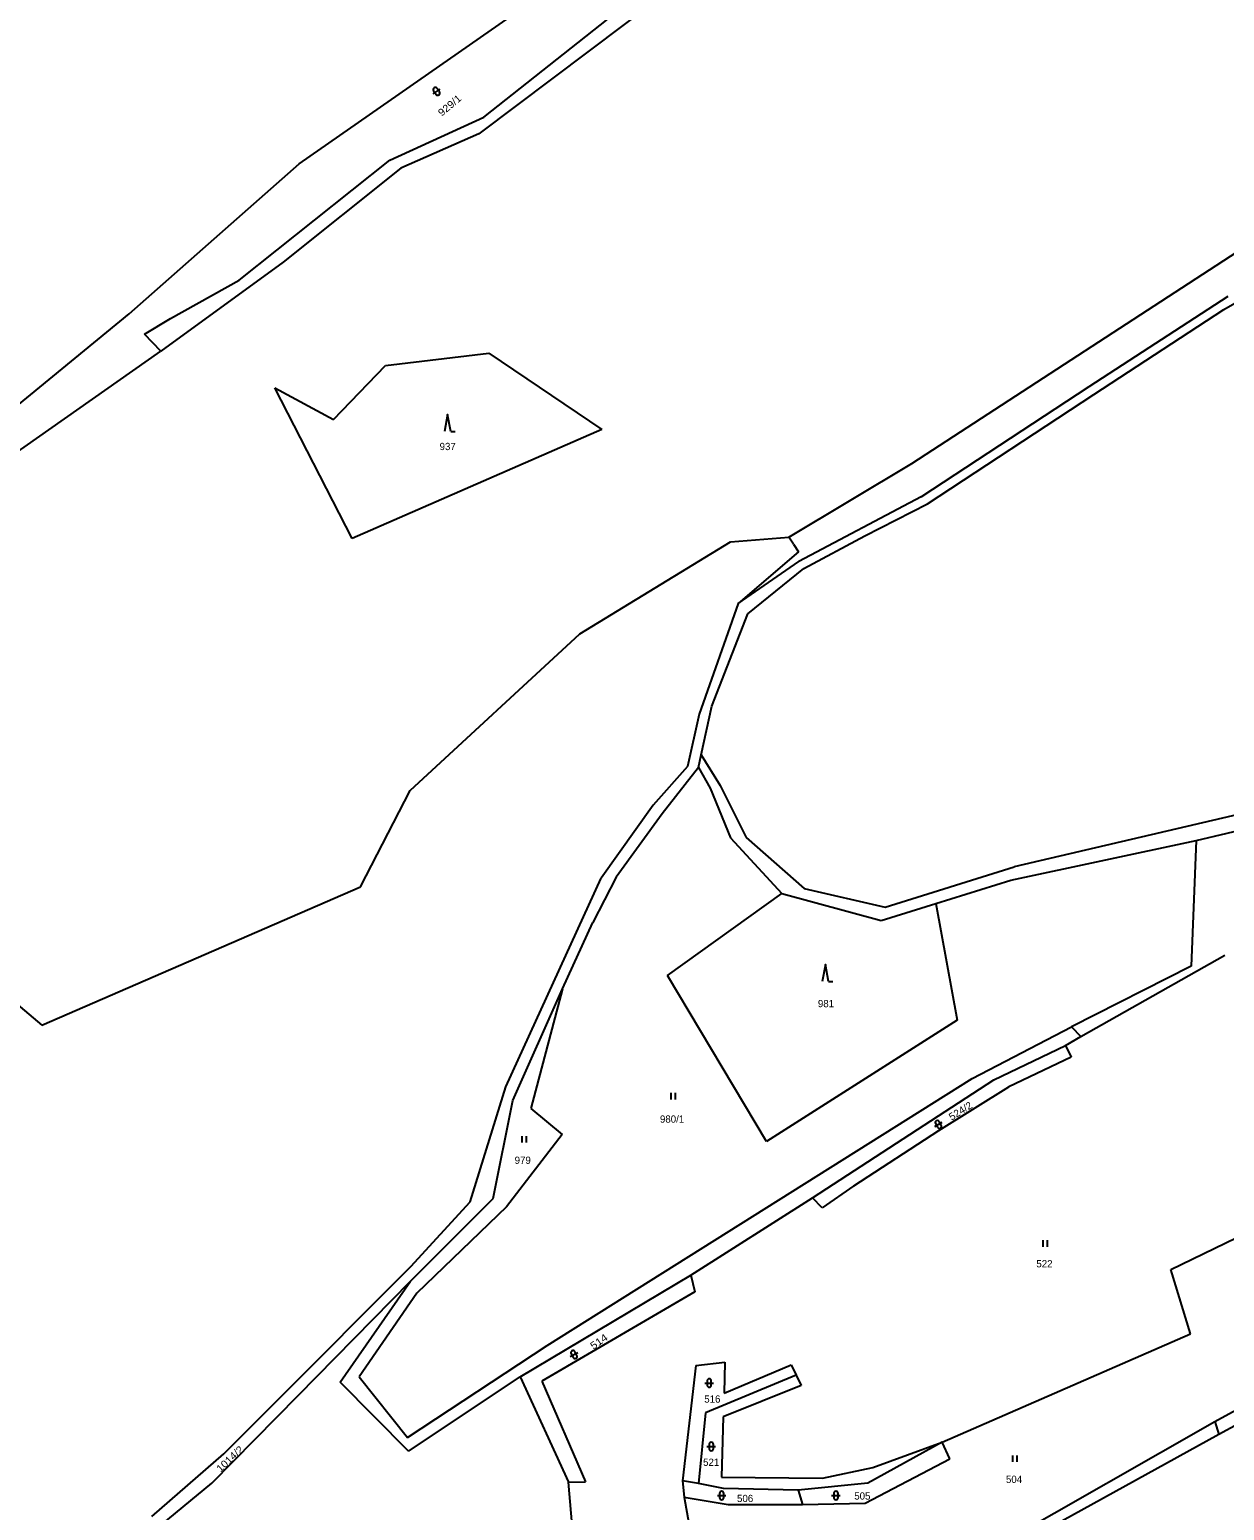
# Model space of a CAD drawing. Extents: x -744132 to -742433, y -984679 to -982287.
# Drawn here: x -743720.7 to -743440.4, y -983707.4 to -983360 of the extents above; entities that cross this region are included whole.
import ezdxf

# ---------------------------------------------------------------- set-up
doc = ezdxf.new("R2010")
doc.units = 0
doc.header["$LTSCALE"] = 0.68
doc.layers.add('1', color=7, linetype='Continuous', lineweight=25)
doc.layers.add('3', color=7, linetype='Continuous', lineweight=25)
doc.layers.add('2', color=7, linetype='Continuous')

msp = doc.modelspace()

# ---------------------------------------------------------------- linework, layer by layer
at = {"layer": '1'}
for p, q in [((-743614.1, -983380.55), (-743560.21, -983337.88)), ((-743563.34, -983345.36), (-743615.25, -983384.5)), ((-743657.43, -983391.5), (-743594.46, -983347.58)), ((-743636.13, -983390.66), (-743614.1, -983380.55)), ((-743615.25, -983384.5), (-743633.58, -983392.53)), ((-743697.32, -983426.73), (-743657.43, -983391.5)), ((-743671.51, -983418.82), (-743636.13, -983390.66)), ((-743513.68, -983461.85), (-743405.43, -983391.3)), ((-743633.58, -983392.53), (-743661.19, -983414.55)), ((-743440.48, -983425.67), (-743400.81, -983402.85)), ((-743661.19, -983414.55), (-743689.92, -983435.46)), ((-743687.58, -983427.84), (-743671.51, -983418.82)), ((-743472.08, -983443.75), (-743439.53, -983422.56)), ((-743471.02, -983445.6), (-743440.48, -983425.67)), ((-743723.53, -983448.22), (-743697.32, -983426.73)), ((-743693.75, -983431.44), (-743687.58, -983427.84)), ((-743689.92, -983435.46), (-743693.75, -983431.44)), ((-743729.35, -983463.19), (-743689.92, -983435.46)), ((-743637.19, -983438.85), (-743612.94, -983435.94)), ((-743612.94, -983435.94), (-743586.41, -983453.84)), ((-743649.36, -983451.49), (-743637.19, -983438.85)), ((-743663.12, -983444.04), (-743649.36, -983451.49)), ((-743645.01, -983479.43), (-743663.12, -983444.04)), ((-743511.48, -983469.61), (-743472.08, -983443.75)), ((-743510.03, -983471.31), (-743471.02, -983445.6)), ((-743586.41, -983453.84), (-743645.01, -983479.43)), ((-743542.57, -983479.1), (-743513.68, -983461.85)), ((-743511.48, -983469.61), (-743540.2, -983484.82)), ((-743524.75, -983478.76), (-743510.03, -983471.31)), ((-743591.6, -983501.75), (-743556.27, -983480.21)), ((-743556.27, -983480.21), (-743542.57, -983479.1)), ((-743541.49, -983480.77), (-743542.57, -983479.1)), ((-743541.49, -983480.77), (-743540.27, -983482.58)), ((-743539.01, -983486.42), (-743524.75, -983478.76)), ((-743540.27, -983482.58), (-743554.45, -983494.7)), ((-743554.45, -983494.7), (-743540.2, -983484.82)), ((-743552.2, -983497.05), (-743539.01, -983486.42)), ((-743554.45, -983494.7), (-743563.6, -983520.61)), ((-743560.64, -983518.75), (-743552.2, -983497.05)), ((-743631.38, -983538.54), (-743591.6, -983501.75)), ((-743563.12, -983530.19), (-743560.64, -983518.75)), ((-743563.6, -983520.61), (-743566.33, -983532.9)), ((-743563.76, -983533.13), (-743563.12, -983530.19)), ((-743563.12, -983530.19), (-743558.67, -983537.33)), ((-743566.33, -983532.9), (-743574.36, -983541.99)), ((-743563.76, -983533.13), (-743572.31, -983544.01)), ((-743563.76, -983533.13), (-743561.01, -983537.99)), ((-743558.67, -983537.33), (-743552.59, -983549.58)), ((-743643.04, -983561.17), (-743631.38, -983538.54)), ((-743561.01, -983537.99), (-743556.24, -983549.65)), ((-743409.37, -983537.63), (-743489.7, -983556.43)), ((-743446.97, -983550.29), (-743405.77, -983540.41)), ((-743574.36, -983541.99), (-743586.57, -983559.09)), ((-743572.31, -983544.01), (-743583.1, -983558.89)), ((-743556.24, -983549.65), (-743544.2, -983562.66)), ((-743552.59, -983549.58), (-743538.97, -983561.54)), ((-743490.48, -983559.54), (-743446.97, -983550.29)), ((-743446.97, -983550.29), (-743448.16, -983579.71)), ((-743762.21, -983556.11), (-743717.8, -983593.58)), ((-743519.94, -983565.92), (-743489.7, -983556.43)), ((-743717.8, -983593.58), (-743643.04, -983561.17)), ((-743608.97, -983608.04), (-743586.57, -983559.09)), ((-743583.1, -983558.89), (-743588.55, -983569.5)), ((-743538.97, -983561.54), (-743519.94, -983565.92)), ((-743508.06, -983565.05), (-743490.48, -983559.54)), ((-743571, -983581.95), (-743544.2, -983562.66)), ((-743544.2, -983562.66), (-743520.91, -983569.03)), ((-743520.91, -983569.03), (-743508.06, -983565.05)), ((-743508.06, -983565.05), (-743503.04, -983592.39)), ((-743595.62, -983585.1), (-743588.55, -983569.5)), ((-743474.03, -983596.28), (-743440.28, -983577.14)), ((-743547.82, -983620.87), (-743571, -983581.95)), ((-743448.16, -983579.71), (-743476.24, -983593.96)), ((-743607.28, -983611.24), (-743595.62, -983585.1)), ((-743595.62, -983585.1), (-743603.12, -983613.14)), ((-743503.04, -983592.39), (-743547.82, -983620.87)), ((-743499.57, -983606.11), (-743476.24, -983593.96)), ((-743477.67, -983598.35), (-743474.03, -983596.28)), ((-743476.24, -983593.96), (-743474.03, -983596.28)), ((-743494.47, -983606.42), (-743477.67, -983598.35)), ((-743477.67, -983598.35), (-743476.35, -983601.11)), ((-743476.35, -983601.11), (-743490.91, -983608.08)), ((-743599.22, -983668.73), (-743499.57, -983606.11)), ((-743536.97, -983634.06), (-743494.47, -983606.42)), ((-743617.28, -983635), (-743608.97, -983608.04)), ((-743507.34, -983618.26), (-743490.91, -983608.08)), ((-743611.88, -983634.28), (-743607.28, -983611.24)), ((-743603.12, -983613.14), (-743595.76, -983619.23)), ((-743595.76, -983619.23), (-743608.83, -983636.23)), ((-743527.31, -983631.31), (-743507.34, -983618.26)), ((-743527.31, -983631.31), (-743534.72, -983636.43)), ((-743631.32, -983653.65), (-743611.88, -983634.28)), ((-743565.54, -983652.25), (-743536.97, -983634.06)), ((-743534.72, -983636.43), (-743536.97, -983634.06)), ((-743452.95, -983650.89), (-743413.28, -983631.64)), ((-743631.22, -983650.19), (-743617.28, -983635)), ((-743608.83, -983636.23), (-743629.86, -983656.48)), ((-743662.98, -983682.06), (-743631.22, -983650.19)), ((-743448.36, -983665.98), (-743452.95, -983650.89)), ((-743657.67, -983680.47), (-743631.32, -983653.65)), ((-743647.82, -983677.33), (-743631.32, -983653.65)), ((-743605.55, -983676.07), (-743565.54, -983652.25)), ((-743565.54, -983652.25), (-743564.64, -983656.13)), ((-743629.86, -983656.48), (-743643.39, -983676.08)), ((-743564.64, -983656.13), (-743600.51, -983677.08)), ((-743506.6, -983691.42), (-743448.36, -983665.98)), ((-743632.02, -983690.34), (-743599.22, -983668.73)), ((-743564.38, -983673.42), (-743557.56, -983672.63)), ((-743557.56, -983672.63), (-743557.71, -983679.94)), ((-743442.59, -983686.58), (-743415.63, -983671.71)), ((-743643.39, -983676.08), (-743632.02, -983690.34)), ((-743631.75, -983693.51), (-743605.55, -983676.07)), ((-743605.55, -983676.07), (-743594.23, -983700.82)), ((-743564.38, -983673.42), (-743567.48, -983700.48)), ((-743540.83, -983675.69), (-743562.07, -983684.55)), ((-743557.71, -983679.94), (-743542.01, -983673.25)), ((-743542.01, -983673.25), (-743540.83, -983675.69)), ((-743540.83, -983675.69), (-743539.63, -983678.14)), ((-743416.77, -983676.1), (-743441.65, -983689.59)), ((-743631.75, -983693.51), (-743647.82, -983677.33)), ((-743600.51, -983677.08), (-743590.22, -983700.75)), ((-743539.63, -983678.14), (-743557.98, -983685.48)), ((-743677.95, -983701.07), (-743657.67, -983680.47)), ((-743675.09, -983694.16), (-743662.98, -983682.06)), ((-743562.07, -983684.55), (-743563.77, -983701.11)), ((-743557.98, -983685.48), (-743558.37, -983699.63)), ((-743493.35, -983715.46), (-743442.59, -983686.58)), ((-743442.59, -983686.58), (-743441.65, -983689.59)), ((-743441.65, -983689.59), (-743492.49, -983717.63)), ((-743506.6, -983691.42), (-743523.99, -983701.05)), ((-743522.88, -983697.39), (-743506.6, -983691.42)), ((-743504.79, -983695.36), (-743506.6, -983691.42)), ((-743691.96, -983708.83), (-743675.09, -983694.16)), ((-743524.62, -983705.75), (-743504.79, -983695.36)), ((-743594.23, -983700.82), (-743590.22, -983700.75)), ((-743563.77, -983701.11), (-743567.48, -983700.48)), ((-743567.48, -983700.48), (-743567.11, -983704.28)), ((-743558.37, -983699.63), (-743534.66, -983699.87)), ((-743534.66, -983699.87), (-743522.88, -983697.39)), ((-743691.4, -983712.12), (-743677.95, -983701.07)), ((-743591.31, -983735.46), (-743594.23, -983700.82)), ((-743557.89, -983702.29), (-743563.77, -983701.11)), ((-743540.38, -983702.68), (-743557.89, -983702.29)), ((-743523.99, -983701.05), (-743540.38, -983702.68)), ((-743540.38, -983702.68), (-743539.37, -983706.01)), ((-743567.11, -983704.28), (-743556.77, -983706.01)), ((-743567.11, -983704.28), (-743561.89, -983733.64)), ((-743556.77, -983706.01), (-743539.37, -983706.01)), ((-743539.37, -983706.01), (-743524.62, -983705.75))]:
    msp.add_line(p, q, dxfattribs=at)
at = {"layer": '3'}
for p, q in [((-743626.023, -983375.116), (-743624.383, -983373.968)), ((-743624.506, -983374.665), (-743625.08, -983373.845)), ((-743625.9, -983374.419), (-743625.326, -983375.239)), ((-743621.85, -983454.33), (-743620.854, -983454.33)), ((-743533.24, -983583.36), (-743532.244, -983583.36)), ((-743570.151, -983610.99), (-743570.151, -983609.49)), ((-743569.15, -983610.99), (-743569.15, -983609.49)), ((-743508.336, -983617.366), (-743506.602, -983616.364)), ((-743508.153, -983616.682), (-743507.653, -983617.549)), ((-743506.786, -983617.048), (-743507.286, -983616.181)), ((-743605.121, -983621.12), (-743605.121, -983619.62)), ((-743604.12, -983621.12), (-743604.12, -983619.62)), ((-743482.871, -983645.56), (-743482.871, -983644.06)), ((-743481.87, -983645.56), (-743481.87, -983644.06)), ((-743593.82, -983671.342), (-743592.069, -983670.371)), ((-743593.625, -983670.661), (-743593.139, -983671.537)), ((-743592.264, -983671.052), (-743592.749, -983670.176)), ((-743562.241, -983677.541), (-743560.239, -983677.541)), ((-743561.741, -983677.041), (-743561.741, -983678.042)), ((-743560.739, -983678.042), (-743560.739, -983677.041)), ((-743561.761, -983692.441), (-743559.759, -983692.441)), ((-743561.261, -983691.941), (-743561.261, -983692.942)), ((-743560.259, -983692.942), (-743560.259, -983691.941)), ((-743490.031, -983696.01), (-743490.031, -983694.51)), ((-743489.03, -983696.01), (-743489.03, -983694.51)), ((-743559.321, -983703.931), (-743557.319, -983703.931)), ((-743558.821, -983703.431), (-743558.821, -983704.432)), ((-743557.819, -983704.432), (-743557.819, -983703.431)), ((-743532.521, -983703.931), (-743530.519, -983703.931)), ((-743532.021, -983703.431), (-743532.021, -983704.432)), ((-743531.019, -983704.432), (-743531.019, -983703.431))]:
    msp.add_line(p, q, dxfattribs=at)
for points in [[(-743621.85, -983454.33), (-743622.6, -983450.33), (-743623.35, -983454.33)], [(-743533.24, -983583.36), (-743533.99, -983579.36), (-743534.74, -983583.36)]]:
    msp.add_lwpolyline(points, dxfattribs=at)
for centre, start, end in [((-743625.4898, -983374.132), 35, 215), ((-743624.9163, -983374.9512), 215, 34.98789), ((-743507.7196, -983616.4317), 30, 210), ((-743507.2195, -983617.2978), 210, 29.98788), ((-743593.1868, -983670.4189), 29, 209), ((-743592.702, -983671.2935), 209, 28.98789), ((-743561.24, -983677.0409), 0, 180), ((-743561.24, -983678.0409), 180, 359.98789), ((-743560.76, -983691.9409), 0, 180), ((-743560.76, -983692.9409), 180, 359.98789), ((-743558.32, -983703.4309), 0, 180), ((-743531.52, -983703.4309), 0, 180), ((-743558.32, -983704.4309), 180, 359.98789), ((-743531.52, -983704.4309), 180, 359.98789)]:
    msp.add_arc(centre, 0.5, start, end, dxfattribs=at)

# ---------------------------------------------------------------- texts
at = {"layer": '2'}
for s, rotation, width, p in [('929/1', 40, 1.1, (-743623.986, -983380.465)), ('524/2', 32, 1.05, (-743504.364, -983616.02)), ('514', 35, 1.15, (-743588.416, -983669.758)), ('1014/2', 43, 1.1, (-743675.9, -983698.57))]:
    msp.add_text(s, height=1.7, rotation=rotation, dxfattribs=dict(at, width=width)).set_placement(p)
for s, p in [('937', (-743624.49, -983458.675)), ('981', (-743535.74, -983589.375)), ('980/1', (-743572.79, -983616.465)), ('979', (-743606.88, -983626.125)), ('522', (-743484.49, -983650.405)), ('516', (-743562.4, -983682.145)), ('521', (-743562.67, -983696.975)), ('504', (-743491.62, -983700.985)), ('506', (-743554.71, -983705.465)), ('505', (-743527.21, -983704.885))]:
    msp.add_text(s, height=1.7, dxfattribs=at).set_placement(p)

doc.saveas('drawing.dxf')
